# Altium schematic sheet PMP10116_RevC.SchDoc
size 431 x 279 mm; Date: Not shown in title block; ApprovedBy: Not shown in title block; CheckedBy: Not shown in title block; Author: Not shown in title block; CompanyName: Not shown in title block; Engineer: Not shown in title block; Organization: Not shown in title block; Address1: Not shown in title block; Address2: Not shown in title block; Address3: Not shown in title block; Address4: Not shown in title block; DocumentNumber: 1; Revision: Use project parameter SCH_Rev; SheetNumber: 2; SheetTotal: 3; PageSetup: Record=PageOptions¦CenterHorizontal=True¦CenterVertical=True¦PrintScale=1.00¦XCorrection=1.00¦YCorrection=1.00¦PrintKind=0¦BorderSize=5000000¦LeftOffset=0¦BottomOffset=0¦Orientation=2¦PaperLength=1000¦PaperWidth=1000¦Scale=100¦PaperSource=15¦PrintQuality=600¦MediaType=1¦DitherType=10¦PaperKind=Letter¦PrintScaleMode=1
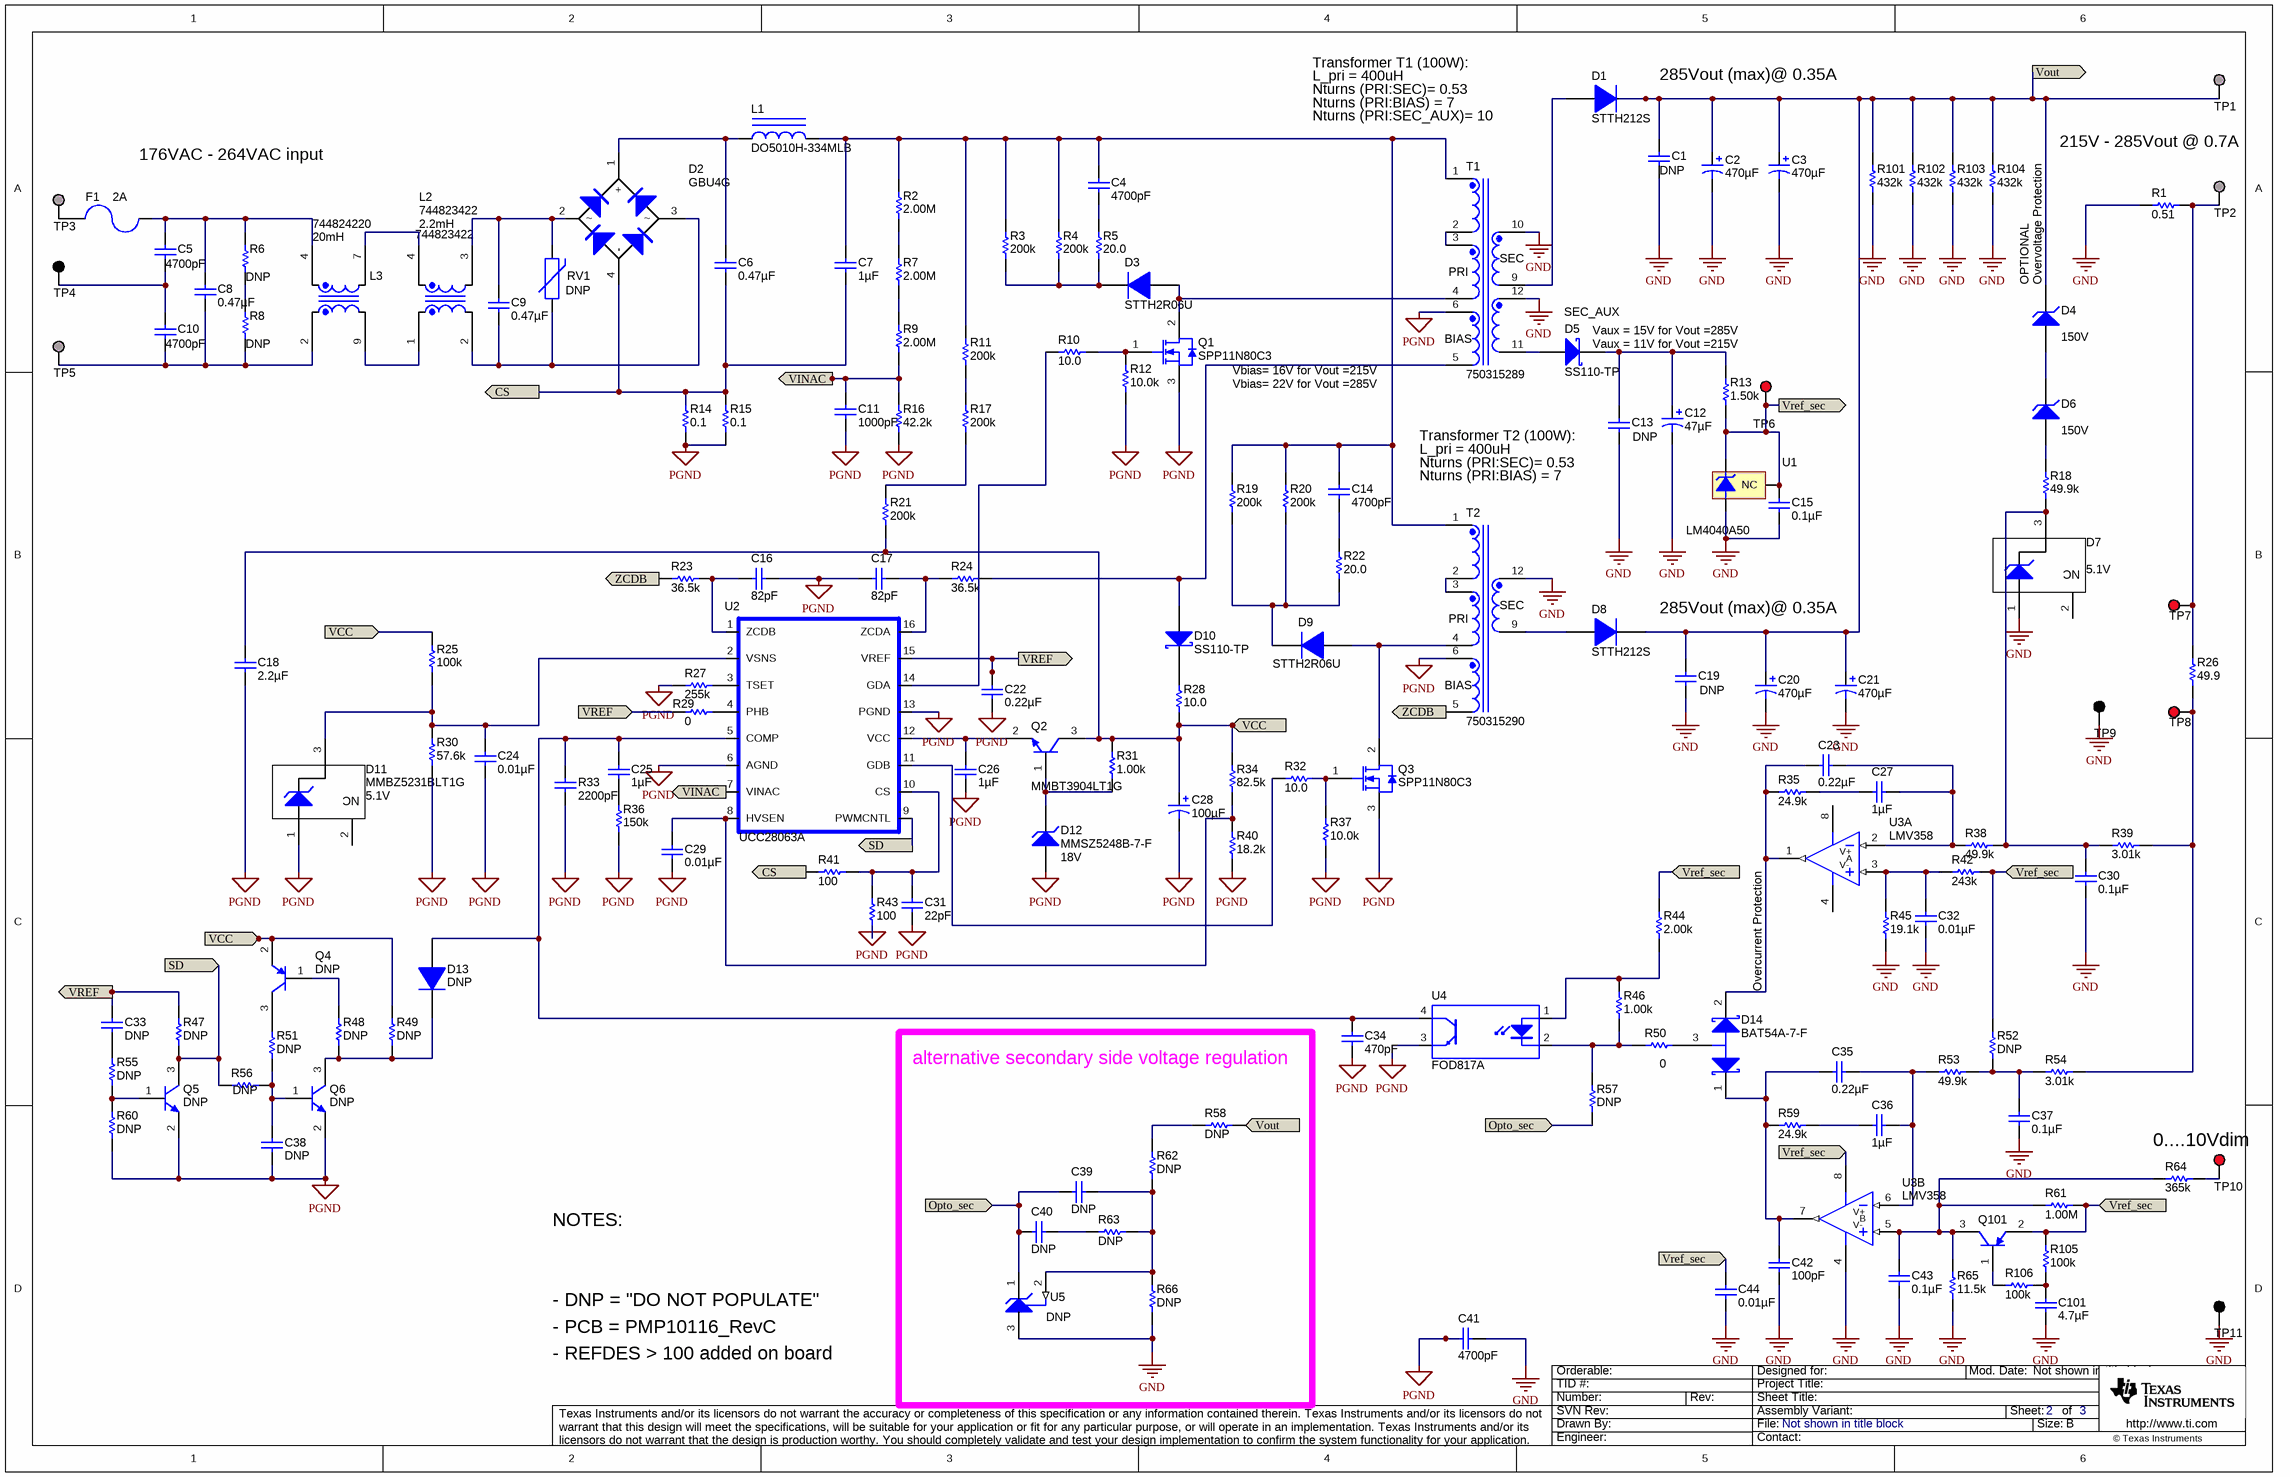
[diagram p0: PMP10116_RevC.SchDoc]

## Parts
C1  value DNP  [1210]  (hidden comment: Used in BOM report)
C2  ValueDisplayed: 470µF  [KMQ_3500x3000]  (hidden comment: EKMQ351VSN471MA30S)
C3  ValueDisplayed: 470µF  [KMQ_3500x3000]  (hidden comment: EKMQ351VSN471MA30S)
C4  ValueDisplayed: 4700pF  [1206]  (hidden comment: GRM31BR72J472KW01L)
C5  ValueDisplayed: 4700pF  [VY2_1250x500x1650]  (hidden comment: VY2472M49Y5US63V7)
C6  ValueDisplayed: 0.47µF  [B32923_16.5mm]  (hidden comment: B32923C3474M)
C7  ValueDisplayed: 1µF  [B32923_20.5mm]  (hidden comment: B32923C3105M)
C8  ValueDisplayed: 0.47µF  [B32923_16.5mm]  (hidden comment: B32923C3474K)
C9  ValueDisplayed: 0.47µF  [B32923_16.5mm]  (hidden comment: B32923C3474K)
C10  ValueDisplayed: 4700pF  [VY2_1250x500x1650]  (hidden comment: VY2472M49Y5US63V7)
C11  ValueDisplayed: 1000pF  [0603]  (hidden comment: 06035A102KAT2A)
C12  ValueDisplayed: 47µF  [SM_RADIAL_E]  (hidden comment: EEE-FC1E470P)
C13  value DNP  [1206]  (hidden comment: Used in BOM report)
C14  ValueDisplayed: 4700pF  [1206]  (hidden comment: GRM31BR72J472KW01L)
C15  ValueDisplayed: 0.1µF  [0603]  (hidden comment: 06035C104KAT2A)
C16  ValueDisplayed: 82pF  [0603]  (hidden comment: GRM1885C1H820JA01D)
C17  ValueDisplayed: 82pF  [0603]  (hidden comment: GRM1885C1H820JA01D)
C18  ValueDisplayed: 2.2µF  [1210_280]  (hidden comment: C3225X7R1H225K250AB)
C19  value DNP  [1210]  (hidden comment: Used in BOM report)
C20  ValueDisplayed: 470µF  [KMQ_3500x3000]  (hidden comment: EKMQ351VSN471MA30S)
C21  ValueDisplayed: 470µF  [KMQ_3500x3000]  (hidden comment: EKMQ351VSN471MA30S)
C22  ValueDisplayed: 0.22µF  [0805]  (hidden comment: C1608X7R1H224K080AB)
C23  ValueDisplayed: 0.22µF  [0603]  (hidden comment: GRM188R71E224KA88D)
C24  ValueDisplayed: 0.01µF  [0603]  (hidden comment: C0603C103J5RACTU)
C25  ValueDisplayed: 1µF  [0805_HV]  (hidden comment: GRM21BR71H105KA12L)
C26  ValueDisplayed: 1µF  [0805_HV]  (hidden comment: C2012X7R1H105K125AB)
C27  ValueDisplayed: 1µF  [0805_HV]  (hidden comment: GRM21BR71C105KA01L)
C28  ValueDisplayed: 100µF  [SM_RADIAL_G]  (hidden comment: EEE-FC1V101P)
C29  ValueDisplayed: 0.01µF  [0603]  (hidden comment: C0603C103J5RACTU)
C30  ValueDisplayed: 0.1µF  [0603]  (hidden comment: C0603C104K5RACTU)
C31  ValueDisplayed: 22pF  [0603]  (hidden comment: 06035A220JAT2A)
C32  ValueDisplayed: 0.01µF  [0603]  (hidden comment: GRM188R71H103KA01D)
C33  ValueDisplayed: DNP  [0805_HV]  (hidden comment: GRM21BR71H474KA88L)
C34  ValueDisplayed: 470pF  [0603]  (hidden comment: GRM188R71H471KA01D)
C35  ValueDisplayed: 0.22µF  [0603]  (hidden comment: GRM188R71E224KA88D)
C36  ValueDisplayed: 1µF  [0805_HV]  (hidden comment: GRM21BR71C105KA01L)
C37  ValueDisplayed: 0.1µF  [0603]  (hidden comment: C0603C104K5RACTU)
C38  ValueDisplayed: DNP  [0805_HV]  (hidden comment: GRM216R71H103KA01D)
C39  ValueDisplayed: DNP  [0805_HV]  (hidden comment: 08055C473JAT2A)
C40  ValueDisplayed: DNP  [0805_HV]  (hidden comment: C2012X5R1E475K125AB)
C41  ValueDisplayed: 4700pF  [VY2_1250x500x1650]  (hidden comment: VY2472M49Y5US63V7)
C42  ValueDisplayed: 100pF  [0603]  (hidden comment: C1608C0G1H101J)
C43  ValueDisplayed: 0.1µF  [0603]  (hidden comment: 06035C104KAT2A)
C44  ValueDisplayed: 0.01µF  [0603]  (hidden comment: GRM188R71H103KA01D)
C101  ValueDisplayed: 4.7µF  [1206]  (hidden comment: C3216X7R1E475K)
D1  STTH212S  [SMC]
D2  GBU4G  [GBU]
D3  STTH2R06U  [SMB]
D4  value 150V  [SMA]  (hidden comment: 3smaj5953b)
D5  SS110-TP  [SMA]
D6  value 150V  [SMA]  (hidden comment: 3smaj5953b)
D7  value 5.1V  [SOT-23]  (hidden comment: MMBZ5230BLT1G)
D8  STTH212S  [SMC]
D9  STTH2R06U  [SMB]
D10  SS110-TP  [SMA]
D11  MMBZ5231BLT1G  value 5.1V  [SOT-23]
D12  MMSZ5248B-7-F  value 18V  [SOD-123]
D13  DNP  [SOD-123]
D14  BAT54A-7-F  [SOT-23]
F1  value 2A  [FUSE_372]  (hidden comment: 38312000000)
L1  DO5010H-334MLB  [DO5010H]
L2  744823422  ValueDisplayed: 2.2mH  [IND_WE-CMB_M]
L3  744824220  value 20mH  [IND_WE-CMB_L]
Q1  SPP11N80C3  [TO-220FP]
Q2  MMBT3904LT1G  [SOT-23]
Q3  SPP11N80C3  [TO-220FP]
Q4  DNP  [SOT-23]
Q5  DNP  [SOT-23]
Q6  DNP  [SOT-23]
Q101  MMBT3906-7-F  [SOT-23]  (value not drawn)
R1  value 0.51  [1210M]  (hidden comment: MCR25JZHFLR510)
R2  ValueDisplayed: 2.00M  [0805_HV]  (hidden comment: CRCW08052M00FKEA)
R3  ValueDisplayed: 200k  [2010]  (hidden comment: CRCW2010200KJNEF)
R4  ValueDisplayed: 200k  [2010]  (hidden comment: CRCW2010200KJNEF)
R5  ValueDisplayed: 20.0  [2010]  (hidden comment: CRCW201020R0FKEF)
R6  value DNP  [1206]  (hidden comment: CRCW1206470KJNEA)
R7  ValueDisplayed: 2.00M  [0805_HV]  (hidden comment: CRCW08052M00FKEA)
R8  value DNP  [1206]  (hidden comment: CRCW1206470KJNEA)
R9  ValueDisplayed: 2.00M  [0805_HV]  (hidden comment: CRCW08052M00FKEA)
R10  ValueDisplayed: 10.0  [0805_HV]  (hidden comment: CRCW080510R0FKEA)
R11  value 200k  [1206]  (hidden comment: CRCW1206200KFKEA)
R12  ValueDisplayed: 10.0k  [0805_HV]  (hidden comment: CRCW080510K0FKEA)
R13  value 1.50k  [0603]  (hidden comment: CRCW06031K50FKEA)
R14  ValueDisplayed: 0.1  [1210M]  (hidden comment: ERJ-L14KF10CU)
R15  ValueDisplayed: 0.1  [1210M]  (hidden comment: ERJ-L14KF10CU)
R16  ValueDisplayed: 42.2k  [0805_HV]  (hidden comment: CRCW080542K2FKEA)
R17  value 200k  [1206]  (hidden comment: CRCW1206200KFKEA)
R18  ValueDisplayed: 49.9k  [0603]  (hidden comment: CRCW060349K9FKEA)
R19  ValueDisplayed: 200k  [2010]  (hidden comment: CRCW2010200KJNEF)
R20  ValueDisplayed: 200k  [2010]  (hidden comment: CRCW2010200KJNEF)
R21  value 200k  [1206]  (hidden comment: CRCW1206200KFKEA)
R22  ValueDisplayed: 20.0  [2010]  (hidden comment: CRCW201020R0FKEF)
R23  ValueDisplayed: 36.5k  [0603]  (hidden comment: CRCW060336K5FKEA)
R24  ValueDisplayed: 36.5k  [0603]  (hidden comment: CRCW060336K5FKEA)
R25  ValueDisplayed: 100k  [0603]  (hidden comment: CRCW0603100KFKEA)
R26  value 49.9  [0603]  (hidden comment: CRCW060349R9FKEA)
R27  ValueDisplayed: 255k  [0603]  (hidden comment: CRCW0603255KFKEA)
R28  value 10.0  [0805_HV]  (hidden comment: CRCW080510R0FKEA)
R29  ValueDisplayed: 0  [0603]  (hidden comment: CRCW06030000Z0EA)
R30  ValueDisplayed: 57.6k  [0603]  (hidden comment: CRCW060357K6FKEA)
R31  value 1.00k  [0603]  (hidden comment: CRCW06031K00FKEA)
R32  ValueDisplayed: 10.0  [0805_HV]  (hidden comment: CRCW080510R0FKEA)
R33  ValueDisplayed: 2200pF  [0603]  (hidden comment: C0603C222K5RACTU)
R34  ValueDisplayed: 82.5k  [0603]  (hidden comment: CRCW060382K5FKEA)
R35  ValueDisplayed: 24.9k  [0603]  (hidden comment: CRCW060324K9FKEA)
R36  ValueDisplayed: 150k  [0603]  (hidden comment: CRCW0603150KFKEA)
R37  ValueDisplayed: 10.0k  [0805_HV]  (hidden comment: CRCW080510K0FKEA)
R38  ValueDisplayed: 49.9k  [0603]  (hidden comment: RC0603FR-0749K9L)
R39  ValueDisplayed: 3.01k  [0603]  (hidden comment: CRCW06033K01FKEA)
R40  ValueDisplayed: 18.2k  [0603]  (hidden comment: CRCW060318K2FKEA)
R41  ValueDisplayed: 100  [0603]  (hidden comment: CRCW0603100RFKEA)
R42  ValueDisplayed: 243k  [0603]  (hidden comment: CRCW0603243KFKEA)
R43  ValueDisplayed: 100  [0603]  (hidden comment: CRCW0603100RFKEA)
R44  ValueDisplayed: 2.00k  [0603]  (hidden comment: CRCW06032K00FKEA)
R45  ValueDisplayed: 19.1k  [0603]  (hidden comment: CRCW060319K1FKEA)
R46  value 1.00k  [0603]  (hidden comment: CRCW06031K00FKEA)
R47  ValueDisplayed: DNP  [0603]  (hidden comment: CRCW060310K0FKEA)
R48  ValueDisplayed: DNP  [0603]  (hidden comment: CRCW060310K0FKEA)
R49  ValueDisplayed: DNP  [0603]  (hidden comment: CRCW0603200RFKEA)
R50  value 0  [0603]  (hidden comment: RC0603FR-072KL)
R51  ValueDisplayed: DNP  [0603]  (hidden comment: CRCW060310K0FKEA)
R52  DNP  [0603_HV]
R53  ValueDisplayed: 49.9k  [0603]  (hidden comment: RC0603FR-0749K9L)
R54  ValueDisplayed: 3.01k  [0603]  (hidden comment: CRCW06033K01FKEA)
R55  ValueDisplayed: DNP  [0603]  (hidden comment: CRCW0603100KFKEA)
R56  ValueDisplayed: DNP  [0603]  (hidden comment: CRCW06031K00FKEA)
R57  value DNP  [0603]  (hidden comment: CRCW06030000Z0EA)
R58  value DNP  [0603]  (hidden comment: CRCW060349R9FKEA)
R59  ValueDisplayed: 24.9k  [0603]  (hidden comment: CRCW060324K9FKEA)
R60  ValueDisplayed: DNP  [0603]  (hidden comment: CRCW0603100KFKEA)
R61  ValueDisplayed: 1.00M  [0603]  (hidden comment: CRCW06031M00FKEA)
R62  ValueDisplayed: DNP  [0603]  (hidden comment: CRCW0603200KFKEA)
R63  ValueDisplayed: DNP  [0603]  (hidden comment: CRCW060315K0FKEA)
R64  ValueDisplayed: 365k  [0603]  (hidden comment: CRCW0603365KFKEA)
R65  ValueDisplayed: 11.5k  [0603]  (hidden comment: CRCW060311K5FKEA)
R66  ValueDisplayed: DNP  [0603]  (hidden comment: CRCW06032K43FKEA)
R101  ValueDisplayed: 432k  [CMF50]  (hidden comment: CMF50432K00FHEB)
R102  ValueDisplayed: 432k  [CMF50]  (hidden comment: CMF50432K00FHEB)
R103  ValueDisplayed: 432k  [CMF50]  (hidden comment: CMF50432K00FHEB)
R104  ValueDisplayed: 432k  [CMF50]  (hidden comment: CMF50432K00FHEB)
R105  ValueDisplayed: 100k  [0603]  (hidden comment: CRCW0603100KFKEA)
R106  ValueDisplayed: 100k  [0603]  (hidden comment: CRCW0603100KFKEA)
RV1  value DNP  [VAR_S10K275E2]  (hidden comment: S20K275)
T1  750315289  [WURTH_750315289_90]
T2  750315290  [WURTH_750315289_90]
TP1  Suggest using a net name here  [Keystone1503-2]  (value not drawn)
TP2  Suggest using a net name here  [Keystone1503-2]  (value not drawn)
TP3  Suggest using a net name here  [Keystone1503-2]  (value not drawn)
TP4  5011  [Keystone5011]  (value not drawn)
TP5  Suggest using a net name here  [Keystone1503-2]  (value not drawn)
TP6  5000  [Keystone5000]  (value not drawn)
TP7  5000  [Keystone5000]  (value not drawn)
TP8  5000  [Keystone5000]  (value not drawn)
TP9  5001  [Keystone5001]  (value not drawn)
TP10  5000  [Keystone5000]  (value not drawn)
TP11  5001  [Keystone5001]  (value not drawn)
U1  LM4040A50  [MF03A_N]
U2  UCC28063A  [D0016A_N]
U3  LMV358  [M08A_L]  (parts A,B of 2)
U4  FOD817A  [DIP-4]
U5  value DNP  [DBZ0003A_N]  (hidden comment: TL431AIDBZT)

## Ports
CS (in), CS (out), Opto_sec (in), SD (in), SD (out), VCC (in), VCC (out), VINAC (in), VINAC (out), Vout (in), Vout (out), VREF (in), VREF (out), Vref_sec (in), Vref_sec (out), ZCDB (in), ZCDB (out)

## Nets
GND: C1.2 C2.2(-) C3.2(-) C12.2(-) C13.2 C15.2 C19.2 C20.2(-) C21.2(-) C30.2 C32.2 C37.2 C41.2 C42.2 C43.2 C44.1 C101.2 D7.1(A) R1.2 R45.1 R65.1 R66.1 R101.1 R102.1 R103.1 R104.1 T1.10 T1.12 T2.12 TP9.1 TP11.1 U1.2(-V) U3.4(V-) U5.3(ANODE)
PGND: C11.2 C16.2 C17.1 C18.2 C22.2 C24.2 C26.2 C28.2(-) C29.2 C31.2 C34.2 C38.2 C41.1 D11.1(A) D12.2(A) Q1.3(S) Q3.3(S) Q5.2(E) Q6.2(E) R12.1 R14.1 R15.1 R16.1 R27.1 R30.1 R33.2 R36.1 R37.1 R40.1 R43.1 R60.1 T1.6 T2.6 U2.6(AGND) U2.13(PGND) U4.3(E)
CS: C6.2 C7.2 D2.4(-) R14.2 R15.2 R41.2 ; port CS
Opto_sec: C39.1 C40.2 R57.2 U5.1(CATHODE) ; port Opto_sec
SD: Q5.3(C) R47.1 R56.2 U2.9(PWMCNTL) ; port SD
VCC: C18.1 C28.1(+) Q2.3(C) Q4.2(E) R21.1 R25.2 R28.1 R31.2 R34.2 R49.2 ; port VCC
VINAC: C11.1 R9.1 R16.2 U2.7(VINAC) ; port VINAC
Vout: C1.1 C2.1(+) C3.1(+) C19.1 C20.1(+) C21.1(+) D1.1(K) D4.1(K) D8.1(K) R58.1 R101.2 R102.2 R103.2 R104.2 TP1.1 ; port Vout
VREF: C22.1 C33.1 R29.1 R47.2 U2.15(VREF) ; port VREF
Vref_sec: C15.1 C44.2 Q101.2(E) R13.1 R42.2 R44.1 R52.2 R61.2 R105.2 TP6.1 U1.1(+V) U1.3(NC) U3.8(V+) ; port Vref_sec
ZCDB: R23.1 T2.5 ; port ZCDB
NetC4_1: C4.1 C7.1 C14.1 L1.2 R2.2 R3.2 R4.2 R11.2 R19.2 R20.2 T1.1 T2.1
NetC4_2: C4.2 R5.2
NetC5_1: C5.1 C8.1 F1.1 L3.4 R6.2
NetC5_2: C5.2 C10.1 TP4.1
NetC6_1: C6.1 D2.1(+) L1.1
NetC8_2: C8.2 C10.2 L3.2 R8.1 TP5.1
NetC9_1: C9.1 D2.2 L2.3 RV1.2
NetC9_2: C9.2 D2.3 L2.2 RV1.1
NetC12_1: C12.1(+) C13.1 D5.1(K) R13.2
NetC14_2: C14.2 R22.2
NetC16_1: C16.1 R23.2 U2.1(ZCDB)
NetC17_2: C17.2 R24.2 U2.16(ZCDA)
NetC23_1: C23.1 D14.2(K2) R35.2 U3.1(OUT)
NetC23_2: C23.2 C27.1 R38.2 U3.2(IN-)
NetC24_1: C24.1 D11.3(K) R25.1 R30.2 U2.2(VSNS)
NetC25_1: C25.1 C34.1 D13.2(A) R33.1 U2.5(COMP) U4.4(C)
NetC25_2: C25.2 R36.2
NetC26_1: C26.1 Q2.2(E) U2.12(VCC)
NetC27_2: C27.2 R35.1
NetC29_1: C29.1 R34.1 R40.2 U2.8(HVSEN)
NetC30_1: C30.1 D7.3(K) R18.1 R38.1 R39.1
NetC31_1: C31.1 R41.1 R43.2 U2.10(CS)
NetC32_1: C32.1 R42.1 R45.2 U3.3(IN+)
NetC33_2: C33.2 R55.2
NetC35_1: C35.1 C42.1 D14.1(K1) R59.2 U3.7(OUT)
NetC35_2: C35.2 C36.1 R53.2 U3.6(IN-)
NetC36_2: C36.2 R59.1
NetC37_1: C37.1 R52.1 R53.1 R54.1
NetC38_1: C38.1 Q6.1(B) R51.1 R56.1
NetC39_2: C39.2 R62.1 R63.1 R66.2 U5.2(REF)
NetC40_1: C40.1 R63.2
NetC43_1: C43.1 Q101.3(C) R61.1 R64.1 R65.2 U3.5(IN+)
NetC101_1: C101.1 R105.1 R106.1
NetD1_2: D1.2(A) T1.9
NetD3_1: D3.1(K) R3.1 R4.1 R5.1
NetD3_2: D3.2(A) Q1.2(D) T1.4
NetD4_2: D4.2(A) D6.1(K)
NetD5_2: D5.2(A) T1.11
NetD6_2: D6.2(A) R18.2
NetD8_2: D8.2(A) T2.9
NetD9_1: D9.1(K) R19.1 R20.1 R22.1
NetD9_2: D9.2(A) Q3.2(D) T2.4
NetD10_1: D10.1(K) R28.2
NetD10_2: D10.2(A) R24.1 T1.5
NetD12_1: D12.1(K) Q2.1(B) R31.1
NetD13_1: D13.1(K) Q6.3(C) R48.1 R49.1
NetD14_3: D14.3(A) R50.1
NetF1_2: F1.2 TP3.1
NetL2_1: L2.1 L3.9
NetL2_4: L2.4 L3.7
NetQ1_1: Q1.1(G) R10.2 R12.2
NetQ3_1: Q3.1(G) R32.2 R37.2
NetQ4_1: Q4.1(B) R48.2
NetQ4_3: Q4.3(C) R51.2
NetQ5_1: Q5.1(B) R55.1 R60.2
NetQ101_1: Q101.1(B) R106.2
NetR1_1: R1.1 R26.2 TP2.1 TP7.1
NetR2_1: R2.1 R7.2
NetR6_1: R6.1 R8.2
NetR7_1: R7.1 R9.2
NetR10_1: R10.1 U2.14(GDA)
NetR11_1: R11.1 R17.2
NetR17_1: R17.1 R21.2
NetR26_1: R26.1 R39.2 R54.2 TP8.1
NetR27_2: R27.2 U2.3(TSET)
NetR29_2: R29.2 U2.4(PHB)
NetR32_1: R32.1 U2.11(GDB)
NetR44_2: R44.2 R46.2 U4.1(A)
NetR46_1: R46.1 R50.2 R57.1 U4.2(K)
NetR58_2: R58.2 R62.2
NetR64_2: R64.2 TP10.1
NetT1_2: T1.2 T1.3
NetT2_2: T2.2 T2.3

Not connected (* = marked no-connect by the designer): D7 2(NC); D11 2(NC)

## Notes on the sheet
- Transformer T1 (100W):
- L_pri = 400uH
- Nturns (PRI:SEC)= 0.53
- 285Vout (max)@ 0.35A
- 176VAC - 264VAC input
- Nturns (PRI:SEC_AUX)= 10
- Nturns (PRI:BIAS) = 7
- 215V - 285Vout @ 0.7A
- (near T1) PRI
- (near T1) SEC
- (near D4) OPTIONAL
- Overvoltage Protection
- (near T1) BIAS
- (near D5) SEC_AUX
- (near D5) Vaux = 15V for Vout =285V
- (near D5) Vaux = 11V for Vout =215V
- Vbias= 16V for Vout =215V
- Vbias= 22V for Vout =285V
- Transformer T2 (100W):
- (near T2) PRI
- (near T2) SEC
- (near T2) BIAS
- Overcurrent Protection
- alternative secondary side voltage regulation
- (near TP10) 0....10Vdim
- NOTES:
- - DNP = "DO NOT POPULATE"
- - PCB = PMP10116_RevC
- - REFDES > 100 added on board

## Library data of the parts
C1 C13 C19 = Capacitor: CAP, CERM, xxxF, xxV, [TempCo], xx%, [PackageReference]; Polarized: N; U/M: EA
C2 C3 C20 C21 = EKMQ351VSN471MA30S: CAP, AL, 470 µF, 350 V, +/- 20%,  ohm, TH; Manufacturer: Chemi-Con; Polarized: Y; CompType: Capacitor; Value: 470uF; U/M: EA; Cap_F: 0.00047; Tolerance_%: 20; Value1: Unknown; VDC_V: 350; Value2: 350V; IRMS_A: 1.4; TaMin_C: -25; TaMax_C: 105; Cap_Case: 35x30mm
C4 C14 = GRM31BR72J472KW01L: CAP, CERM, 4700 pF, 630 V, +/- 10%, X7R, 1206; Manufacturer: MuRata; Polarized: N; CompType: Capacitor; Value: 4700pF; U/M: EA; Cap_F: 0.0000000047; Tolerance_%: 10; Value1: Unknown; VDC_V: 630; Value2: 630V; TaMin_C: -55; TaMax_C: 125
C5 C10 C41 = VY2472M49Y5US63V7: CAP, CERM, 4700 pF, 440 V, +/- 20%, Y5U, TH, 12.5x5mm; Manufacturer: Vishay-Bccomponents; Polarized: N; CompType: Capacitor; Value: 4700pF; U/M: EA; Cap_F: 0.0000000047; Tolerance_%: 20; Value1: Unknown; VDC_V: 440; Value2: 440V; TaMin_C: -40; TaMax_C: 125; Cap_Case: 12.5x5x16.5
C6 = B32923C3474M: CAP, Film, 0.47 µF, 630 V, +/- 20%, TH; Manufacturer: EPCOS Inc; Polarized: N; CompType: Capacitor; Value: 0.47uF; U/M: EA; Cap_F: 0.00000047; Tolerance_%: 20; Value1: Unknown; VDC_V: 630; Value2: 630V; TaMax_C: 110
C7 = B32923C3105M: CAP, Film, 1 µF, 630 V, +/- 20%, 0.018 ohm, TH; Manufacturer: EPCOS Inc; Polarized: N; CompType: Capacitor; Value: 1uF; U/M: EA; Cap_F: 0.000001; Tolerance_%: 20; VDC_V: 630; Value2: 630V; ESR_ohm: 0.018; IRMS_A: 0.097; TaMax_C: 110
C8 C9 = B32923C3474K: CAP, Film, 0.47 µF, 630 V, +/- 10%, TH; Manufacturer: TDK; Polarized: N; CompType: Capacitor; Value: 0.47uF; U/M: EA; Cap_F: 0.00000047; Tolerance_%: 10; Value1: Unknown; VDC_V: 630; Value2: 630V; TaMax_C: 110
C11 = 06035A102KAT2A: CAP, CERM, 1000 pF, 50 V, +/- 10%, C0G/NP0, 0603; Manufacturer: AVX; Polarized: N; CompType: Capacitor; Value: 1000pF; U/M: EA; Cap_F: 0.000000001; Tolerance_%: 10; ESR_ohm: 0.048; Value1: 0.048 ohm; VDC_V: 50; Value2: 50V; TaMin_C: -55; TaMax_C: 125
C12 = EEE-FC1E470P: CAP, AL, 47uF, 25V, +/-20%, 0.4 ohm, SMD; Manufacturer: Panasonic; Polarized: Y; CompType: Capacitor; U/M: EA; Cap_F: 0.000047; Tolerance_%: 20; Value1: 0.4 ohm; VDC_V: 25; ESR_Ohm: 0.4; IRMS_A: 0.15; TaMin_C: -40; TaMax_C: 105; Cap_Case: E
C15 C43 = 06035C104KAT2A: CAP, CERM, 0.1uF, 50V, +/-10%, X7R, 0603; Manufacturer: AVX; Polarized: N; CompType: Capacitor; U/M: EA; Cap_F: 0.0000001; Tolerance_%: 10; Value1: Unknown; VDC_V: 50; TaMin_C: -55; TaMax_C: 125
C16 C17 = GRM1885C1H820JA01D: CAP, CERM, 82 pF, 50 V, +/- 5%, C0G/NP0, 0603; Manufacturer: MuRata; Polarized: N; CompType: Capacitor; Value: 82pF; U/M: EA; Cap_F: 0.000000000082; Tolerance_%: 5; Value1: Unknown; VDC_V: 50; Value2: 50V; TaMin_C: -55; TaMax_C: 125
C18 = C3225X7R1H225K250AB: CAP, CERM, 2.2 µF, 50 V, +/- 10%, X7R, 1210; Manufacturer: TDK; Polarized: N; CompType: Capacitor; Value: 2.2uF; U/M: EA; Cap_F: 0.0000022; Tolerance_%: 10; Value1: Unknown; VDC_V: 50; Value2: 50V; TaMin_C: -55; TaMax_C: 125; Cap_Case: 1210
C22 = GRM21BR71H224KA01L: CAP, CERM, 0.22 µF, 50 V, +/- 10%, X7R, 0805; Manufacturer: MuRata; Polarized: N; CompType: Capacitor; Value: 0.22uF; U/M: EA; Cap_F: 0.00000022; Tolerance_%: 10; Value1: Unknown; VDC_V: 50; Value2: 50V; TaMin_C: -55; TaMax_C: 125
C23 C35 = GRM188R71E224KA88D: CAP, CERM, 0.22 µF, 25 V, +/- 10%, X7R, 0603; Manufacturer: MuRata; Polarized: N; CompType: Capacitor; Value: 0.22uF; U/M: EA; Cap_F: 0.00000022; Tolerance_%: 10; Value1: Unknown; VDC_V: 25; Value2: 25V; TaMin_C: -55; TaMax_C: 125
C24 C29 = C0603C103J5RACTU: CAP, CERM, 0.01 µF, 50 V, +/- 5%, X7R, 0603; Manufacturer: Kemet; Polarized: N; CompType: Capacitor; Value: 0.01uF; U/M: EA; Cap_F: 0.00000001; Tolerance_%: 5; Value1: Unknown; VDC_V: 50; Value2: 50V; TaMin_C: -55; TaMax_C: 125
C25 = GRM21BR71H105KA12L: CAP, CERM, 1 µF, 50 V, +/- 10%, X7R, 0805; Manufacturer: MuRata; Polarized: N; CompType: Capacitor; Value: 1uF; U/M: EA; Cap_F: 0.000001; Tolerance_%: 10; Value1: Unknown; VDC_V: 50; Value2: 50V; TaMin_C: -55; TaMax_C: 125; Cap_Case: 0805
C26 = C2012X7R1H105K125AB: CAP, CERM, 1 µF, 50 V, +/- 10%, X7R, 0805; Manufacturer: TDK; Polarized: N; CompType: Capacitor; Value: 1uF; U/M: EA; Cap_F: 0.000001; Tolerance_%: 10; Value1: Unknown; VDC_V: 50; Value2: 50V; TaMin_C: -55; TaMax_C: 125; Cap_Case: 0805
C27 C36 = GRM21BR71C105KA01L: CAP, CERM, 1 µF, 16 V, +/- 10%, X7R, 0805; Manufacturer: MuRata; Polarized: N; CompType: Capacitor; Value: 1uF; U/M: EA; Cap_F: 0.000001; Tolerance_%: 10; ESR_ohm: 0.003; Value1: 0.003 ohm; VDC_V: 16; Value2: 16V; TaMin_C: -55; TaMax_C: 125; Cap_Case: 0805
C28 = EEE-FC1V101P: CAP, AL, 100 µF, 35 V, +/- 20%, 0.15 ohm, SMD; Manufacturer: Panasonic; Polarized: Y; CompType: Capacitor; Value: 100uF; U/M: EA; Cap_F: 0.0001; Tolerance_%: 20; VDC_V: 35; Value2: 35V; ESR_ohm: 0.15; IRMS_A: 0.22; TaMin_C: -40; TaMax_C: 105; Cap_Case: G
C30 C37 = C0603C104K5RACTU: CAP, CERM, 0.1 µF, 50 V, +/- 10%, X7R, 0603; Manufacturer: Kemet; Polarized: N; CompType: Capacitor; Value: 0.1uF; U/M: EA; Cap_F: 0.0000001; Tolerance_%: 10; Value1: Unknown; VDC_V: 50; Value2: 50V; TaMin_C: -55; TaMax_C: 125
C31 = 06035A220JAT2A: CAP, CERM, 22 pF, 50 V, +/- 5%, C0G/NP0, 0603; Manufacturer: AVX; Polarized: N; CompType: Capacitor; Value: 22pF; U/M: EA; Cap_F: 0.000000000022; Tolerance_%: 5; ESR_ohm: 0.259; Value1: 0.259 ohm; VDC_V: 50; Value2: 50V; TaMin_C: -55; TaMax_C: 125
C32 C44 = GRM188R71H103KA01D: CAP, CERM, 0.01uF, 50V, +/-10%, X7R, 0603; Manufacturer: MuRata; Polarized: N; CompType: Capacitor; U/M: EA; Cap_F: 0.00000001; Tolerance_%: 10; Value1: Unknown; VDC_V: 50; TaMin_C: -55; TaMax_C: 125
C33 = GRM21BR71H474KA88L: CAP, CERM, 0.47 µF, 50 V, +/- 10%, X7R, 0805; Manufacturer: MuRata; Polarized: N; CompType: Capacitor; Value: 0.47uF; U/M: EA; Cap_F: 0.00000047; Tolerance_%: 10; Value1: Unknown; VDC_V: 50; Value2: 50V; TaMin_C: -55; TaMax_C: 125; Cap_Case: 0805
C34 = GRM188R71H471KA01D: CAP, CERM, 470 pF, 50 V, +/- 10%, X7R, 0603; Manufacturer: MuRata; Polarized: N; CompType: Capacitor; Value: 470pF; U/M: EA; Cap_F: 0.00000000047; Tolerance_%: 10; Value1: Unknown; VDC_V: 50; Value2: 50V; TaMin_C: -55; TaMax_C: 125
C38 = GRM216R71H103KA01D: CAP, CERM, 0.01 µF, 50 V, +/- 10%, X7R, 0805; Manufacturer: MuRata; Polarized: N; CompType: Capacitor; Value: 0.01uF; U/M: EA; Cap_F: 0.00000001; Tolerance_%: 10; Value1: Unknown; VDC_V: 50; Value2: 50V; TaMin_C: -55; TaMax_C: 125; Cap_Case: 0805
C39 = 08055C473JAT2A: CAP, CERM, 0.047 µF, 50 V, +/- 5%, X7R, 0805; Manufacturer: AVX; Polarized: N; CompType: Capacitor; Value: 0.047uF; U/M: EA; Cap_F: 0.000000047; Tolerance_%: 5; ESR_ohm: 0.035; Value1: 0.035 ohm; VDC_V: 50; Value2: 50V; TaMin_C: -55; TaMax_C: 125; Cap_Case: 0805
C40 = C2012X5R1E475K125AB: CAP, CERM, 4.7 µF, 25 V, +/- 10%, X5R, 0805; Manufacturer: TDK; Polarized: N; CompType: Capacitor; Value: 4.7uF; U/M: EA; Cap_F: 0.0000047; Tolerance_%: 10; Value1: Unknown; VDC_V: 25; Value2: 25V; TaMin_C: -55; TaMax_C: 85; Cap_Case: 0805
C42 = C1608C0G1H101J: CAP, CERM, 100 pF, 50 V, +/- 5%, C0G/NP0, 0603; Manufacturer: TDK; Polarized: N; CompType: Capacitor; Value: 100pF; U/M: EA; Cap_F: 0.0000000001; Tolerance_%: 5; ESR_ohm: 0.1679; Value1: 0.1679 ohm; VDC_V: 50; Value2: 50V; TaMin_C: -55; TaMax_C: 125
C101 = C3216X7R1E475K: CAP, CERM, 4.7 µF, 25 V, +/- 10%, X7R, 1206; Manufacturer: TDK; Polarized: N; CompType: Capacitor; Value: 4.7uF; U/M: EA; Cap_F: 0.0000047; Tolerance_%: 10; ESR_ohm: 0.0063; Value1: 0.0063 ohm; VDC_V: 25; Value2: 25V; TaMin_C: -55; TaMax_C: 125
D1 D8 = MURS360T3G: Diode, Ultrafast, 1200V, SMC; Manufacturer: ST; U/M: EA; RJC_CperW: 11; Reverse Recovery Time (trr): 75ns; Current - Reverse Leakage @ Vr: 10µA @ 1200V
D2 = GBU4K-E3/45: Diode, Switching-Bridge, 400 V, 4 A, TH; Manufacturer: Vishay-Semiconductor; U/M: EA; Vf_V: 1; Value: 400V; Value1: 4A; Value2: 1V; Io_A: 4; TJmax_C: 150; RJC_CperW: 4.2
D3 D9 = STTH1R06U: Diode, Superfast Rectifier, 600 V, 2A, SMB; Manufacturer: ST Microelectronics; U/M: EA; Value: 600V; Io_A: 1; Vr_V: 600; TJmax_C: 175; RJC_CperW: 25; Speed: Fast Recovery =< 500ns, > 200mA (Io); Reverse Recovery Time (trr): 50ns; Current - Reverse Leakage @ Vr: 2µA @ 600V
D4 D6 = 3SMAJ5941B-TP: Diode, Zener, 150 V, 3 W, SMA; Manufacturer: Micro Commercial Components; SymbolCreator: a0412235; U/M: EA; Power_W: 3; Vz_V: 47; Value1: 3W; Tolerance_%: ±5%; Impedance (Max) (Zzt): 600 Ohm; Current - Reverse Leakage @ Vr: 1µA @ 114V
D5 D10 = SS110-TP: Diode, Schottky, 100V, 1A, SMA; Manufacturer: Micro Commercial Components; U/M: EA; Vf_V: 0.85; Value2: 0.85V; Io_A: 1; Vr_V: 100; TJmax_C: 125
D7 = MMBZ5230BLT1G: Diode, Zener, 4.7V, 225mW, SOT-23; Manufacturer: ON Semiconductor; U/M: EA; Power_W: 0.225; Vz_V: 4.7; Value1: 0.225W; RJA_CperW: 556
D11 = MMBZ5231BLT1G: Diode, Zener, 5.1 V, 225 mW, SOT-23; Manufacturer: ON Semiconductor; U/M: EA; Power_W: 0.225; Vz_V: 5.1; Value1: 0.225W; RJA_CperW: 556
D12 = MMSZ5248B-7-F: Diode, Zener, 18 V, 500 mW, SOD-123; Manufacturer: Diodes Inc.; SymbolCreator: a0412235; U/M: EA; Power_W: 0.5; Vz_V: 18; Value1: 0.5W; RJA_CperW: 350
D13 = 1N4148W-TP: Diode, Switching, 100 V, 0.15 A, SOD-123; Manufacturer: Micro Commercial Components; U/M: EA; Vf_V: 1.25; Value: 100V; Value1: 0.15A; Value2: 1.25V; Io_A: 0.15; Vr_V: 100; TJmax_C: 150
D14 = BAT54A-7-F: Diode, Schottky, 30 V, 0.2 A, SOT-23; Manufacturer: Diodes Inc.; U/M: EA; Vf_V: 0.65; Value: 30V; Value1: 0.2A; Value2: 0.65V; Io_A: 0.2; Vr_V: 30; TJmax_C: 125
F1 = 37211000001: Fuse, 2A, 300 V, TH; Manufacturer: Littelfuse; U/M: EA; OpeningTime_200%_max: 2; Irating_A: 1; Vdrop: 0.11; Soldering_Wave_MaxTemp_C: 260; Soldering_Wave_MaxTime_s: 5; Fuse Type: Board Mount (Cartridge Style Excluded); Voltage Rating - AC: 300V; Response Time: Slow; Breaking Capacity @ Rated Voltage: 100A; Melting I²t: 12; Approvals: cULus, PSE/JET
L1 = DO5010H-334MLB: Inductor, Drum Core, Ferrite, 330 µH, 1 A, 0.56 ohm, SMD; Manufacturer: Coilcraft; Value: 330uH; Ind_H: 330.0E-6; ValueDisplayed: 330µH; Imax_A: 1; Irms: 1A @ 40C rise; Isat: 1.9A @ 10% inductance drop; DCR_ohm: 0.56; Value2: 1A
L2 = 744823210: Coupled inductor, 2.2 mH,; Manufacturer: Wurth Elektronik eiSos; SymbolCreator: a0412235; Ind_H: 10.0E-3; DCR_ohm: 0.125; Isat: 2; Tolerance_%: 30; Value: 2.2mH; Filter Type: Power Line; Irms: 1.5A
L3 = 744824310: Coupled inductor, 20 mH; Manufacturer: Wurth Elektronik; SymbolCreator: a0799628; Ind_H: 10.0E-3; DCR_ohm: 0.105; Isat: 3; Tolerance_%: 30
Q1 Q3 = SPA11N80C3: MOSFET, N-CH, 800 V, 11 A, TO-220FP; Manufacturer: Infineon Technologies; Alternate Manufacturer: None; U/M: EA; ChType: N; Value: 800V; VdsMax_V: 800; Value1: ? ohm; Value2: 64 nC; QgTyp_nC: 64; Vgs_V: 20; IdsMax_A: 11
Q2 = MMBT3904LT1G, ON Semiconductor: Transistor, NPN, 40V, 0.2A, SOT-23; CompType: BJT; PNP: 0; NPN: 1; Vceo_V: 40; Vcesat1_V: 0.3; Value: 0.3V; IcRated_A: 0.2; HfeMax: 400; TaMin_C: -55; TaMax_C: 150; U/M: EA
Q4 Q101 = MMBT3906-7-F, Diodes Inc.: Transistor, PNP, 40 V, 0.2 A, SOT-23; CompType: BJT; PNP: 1; NPN: 0; Vceo_V: 40; Vcesat1_V: 0.25; Value: 40 V; IcRated_A: 0.2; Value1: 0.2 A; HfeMax: 400; TaMin_C: -55; TaMax_C: 150; U/M: EA
Q5 Q6 = MMBT3904, Fairchild Semiconductor: Transistor, NPN, 40 V, 0.2 A, SOT-23; CompType: BJT; PNP: 0; NPN: 1; Vceo_V: 40; Vcesat1_V: 0.2; Value: 40 V; Value1: 0.2 A; HfeMax: 300; TaMin_C: -55; TaMax_C: 150; U/M: EA
R1 = MCR25JZHFLR510: RES, 0.51 ohm, 1%, 0.5W, 1210; Manufacturer: Rohm; CompType: Resistor; Value_Code: R510; Tolerance_%: 1; Power_W: 0.5; TempCo: 200 ppm/C; EIA_Code: E96; U/M: EA
R2 R7 R9 = CRCW08052M00FKEA: RES, 2.00 M, 1%, 0.125 W, 0805; Manufacturer: Vishay-Dale; CompType: Resistor; Value: 2.00Meg; Res_ohm: 2000000; Value_Code: 2M00; Tolerance_%: 1; Power_W: 0.125; Value2: 0.125W; VDC_V: 150; TempCo: 100 ppm/C; EIA_Code: E96; U/M: EA
R3 R4 R19 R20 = CRCW2010200KJNEF: RES, 200 k, 5%, 0.75 W, 2010; Manufacturer: Vishay-Dale; CompType: Resistor; Value: 200k; Res_ohm: 200000; Tolerance_%: 5; Power_W: 0.75; Value2: 0.75W; VDC_V: 400; TempCo: 200 ppm/C; EIA_Code: E24; U/M: EA
R5 R22 = CRCW201020R0FKEF: RES, 20.0, 1%, 0.75 W, 2010; Manufacturer: Vishay-Dale; CompType: Resistor; Value: 20.0; Res_ohm: 20; Value_Code: 20R0; Tolerance_%: 1; Power_W: 0.75; Value2: 0.75W; VDC_V: 400; TempCo: 100 ppm/C; EIA_Code: E96; U/M: EA
R6 R8 = CRCW1206470KJNEA: RES, 470 k, 5%, 0.25 W, 1206; Manufacturer: Vishay-Dale; CompType: Resistor; Res_ohm: 470000; Value_Code: 470k; Tolerance_%: 5; Power_W: 0.25; Value2: 0.25W; VDC_V: 200; TempCo: 200 ppm/C; EIA_Code: E24; U/M: EA
R10 R32 = CRCW080510R0FKEA: RES, 10.0, 1%, 0.125 W, 0805; Manufacturer: Vishay-Dale; CompType: Resistor; Value: 10.0; Res_ohm: 10; Value_Code: 10R0; Tolerance_%: 1; Power_W: 0.125; Value2: 0.125W; VDC_V: 150; TempCo: 100 ppm/C; EIA_Code: E96; U/M: EA
R11 R17 R21 = CRCW1206200KFKEA: RES, 200k ohm, 1%, 0.25W, 1206; Manufacturer: Vishay-Dale; CompType: Resistor; Res_ohm: 200000; Tolerance_%: 1; Power_W: 0.25; VDC_V: 200; TempCo: 100 ppm/C; EIA_Code: E96; U/M: EA
R12 R37 = CRCW080510K0FKEA: RES, 10.0 k, 1%, 0.125 W, 0805; Manufacturer: Vishay-Dale; CompType: Resistor; Value: 10.0k; Res_ohm: 10000; Value_Code: 10k0; Tolerance_%: 1; Power_W: 0.125; Value2: 0.125W; VDC_V: 150; TempCo: 100 ppm/C; EIA_Code: E96; U/M: EA
R13 = CRCW06031K50FKEA: RES, 1.50k ohm, 1%, 0.1W, 0603; Manufacturer: Vishay-Dale; CompType: Resistor; Res_ohm: 1500; Value_Code: 1k50; Tolerance_%: 1; Power_W: 0.1; VDC_V: 75; TempCo: 100 ppm/C; EIA_Code: E96; U/M: EA
R14 R15 = ERJ-L14KF10CU: RES, 0.1, 1%, 0.33 W, 1210; Manufacturer: Panasonic; CompType: Resistor; Value: 0.1; Value_Code: R100; Tolerance_%: 1; Power_W: 0.33; Value2: 0.33W; TempCo: 100 ppm/C; EIA_Code: E96; U/M: EA
R16 = CRCW080542K2FKEA: RES, 42.2 k, 1%, 0.125 W, 0805; Manufacturer: Vishay-Dale; CompType: Resistor; Value: 42.2k; Res_ohm: 42200; Value_Code: 42k2; Tolerance_%: 1; Power_W: 0.125; Value2: 0.125W; VDC_V: 150; TempCo: 100 ppm/C; EIA_Code: E96; U/M: EA
R18 = CRCW060349K9FKEA: RES, 49.9 k, 1%, 0.1 W, 0603; Manufacturer: Vishay-Dale; CompType: Resistor; Value: 49.9k; Res_ohm: 49900; Value_Code: 49k9; Tolerance_%: 1; Power_W: 0.1; Value2: 0.1W; VDC_V: 75; TempCo: 100 ppm/C; EIA_Code: E96; U/M: EA
R23 R24 = CRCW060336K5FKEA: RES, 36.5 k, 1%, 0.1 W, 0603; Manufacturer: Vishay-Dale; CompType: Resistor; Value: 36.5k; Res_ohm: 36500; Value_Code: 36k5; Tolerance_%: 1; Power_W: 0.1; Value2: 0.1W; VDC_V: 75; TempCo: 100 ppm/C; EIA_Code: E96; U/M: EA
R25 R55 R60 R105 R106 = CRCW0603100KFKEA: RES, 100 k, 1%, 0.1 W, 0603; Manufacturer: Vishay-Dale; CompType: Resistor; Value: 100k; Res_ohm: 100000; Tolerance_%: 1; Power_W: 0.1; Value2: 0.1W; VDC_V: 75; TempCo: 100 ppm/C; EIA_Code: E96; U/M: EA
R26 = CRCW060349R9FKEA: RES, 49.9 ohm, 1%, 0.1W, 0603; Manufacturer: Vishay-Dale; CompType: Resistor; Value_Code: 49R9; Tolerance_%: 1; Power_W: 0.1; VDC_V: 75; TempCo: 100 ppm/C; EIA_Code: E96; U/M: EA
R27 = CRCW0603255KFKEA: RES, 255 k, 1%, 0.1 W, 0603; Manufacturer: Vishay-Dale; CompType: Resistor; Value: 255k; Res_ohm: 255000; Tolerance_%: 1; Power_W: 0.1; Value2: 0.1W; VDC_V: 75; TempCo: 100 ppm/C; EIA_Code: E96; U/M: EA
R28 = CRCW080510R0FKEA: RES, 10.0 ohm, 1%, 0.125W, 0805; Manufacturer: Vishay-Dale; CompType: Resistor; Res_ohm: 10; Value_Code: 10R0; Tolerance_%: 1; Power_W: 0.125; VDC_V: 150; TempCo: 100 ppm/C; EIA_Code: E96; U/M: EA
R29 = CRCW06030000Z0EA: RES, 0, 5%, 0.1 W, 0603; Manufacturer: Vishay-Dale; CompType: Resistor; Value: 0; Value_Code: 0000; Tolerance_%: 5; Power_W: 0.1; Value2: 0.1W; VDC_V: 75; TempCo: 200 ppm/C; EIA_Code: E24; U/M: EA
R30 = CRCW060357K6FKEA: RES, 57.6 k, 1%, 0.1 W, 0603; Manufacturer: Vishay-Dale; CompType: Resistor; Value: 57.6k; Res_ohm: 57600; Value_Code: 57k6; Tolerance_%: 1; Power_W: 0.1; Value2: 0.1W; VDC_V: 75; TempCo: 100 ppm/C; EIA_Code: E96; U/M: EA
R31 R46 = CRCW06031K00FKEA: RES, 1.00k ohm, 1%, 0.1W, 0603; Manufacturer: Vishay-Dale; CompType: Resistor; Res_ohm: 1000; Value_Code: 1k00; Tolerance_%: 1; Power_W: 0.1; VDC_V: 75; TempCo: 100 ppm/C; EIA_Code: E96; U/M: EA
R33 = C0603C222K5RACTU: CAP, CERM, 2200 pF, 50 V, +/- 10%, X7R, 0603; Manufacturer: Kemet; Polarized: N; CompType: Capacitor; Value: 2200pF; U/M: EA; Cap_F: 0.0000000022; Tolerance_%: 10; Value1: Unknown; VDC_V: 50; Value2: 50V; TaMin_C: -55; TaMax_C: 125
R34 = CRCW060382K5FKEA: RES, 82.5 k, 1%, 0.1 W, 0603; Manufacturer: Vishay-Dale; CompType: Resistor; Value: 82.5k; Res_ohm: 82500; Value_Code: 82k5; Tolerance_%: 1; Power_W: 0.1; Value2: 0.1W; VDC_V: 75; TempCo: 100 ppm/C; EIA_Code: E96; U/M: EA
R35 R59 = CRCW060324K9FKEA: RES, 24.9 k, 1%, 0.1 W, 0603; Manufacturer: Vishay-Dale; CompType: Resistor; Value: 24.9k; Res_ohm: 24900; Value_Code: 24k9; Tolerance_%: 1; Power_W: 0.1; Value2: 0.1W; VDC_V: 75; TempCo: 100 ppm/C; EIA_Code: E96; U/M: EA
R36 = CRCW0603150KFKEA: RES, 150 k, 1%, 0.1 W, 0603; Manufacturer: Vishay-Dale; CompType: Resistor; Value: 150k; Res_ohm: 150000; Tolerance_%: 1; Power_W: 0.1; Value2: 0.1W; VDC_V: 75; TempCo: 100 ppm/C; EIA_Code: E96; U/M: EA
R38 R53 = RC0603FR-0749K9L: RES, 49.9 k, 1%, 0.1 W, 0603; Manufacturer: Yageo America; CompType: Resistor; Value: 49.9k; Res_ohm: 49900; Value_Code: 49k9; Tolerance_%: 1; Power_W: 0.1; Value2: 0.1W; VDC_V: 150; TempCo: 200 ppm/C; EIA_Code: E96; U/M: EA
R39 R54 = CRCW06033K01FKEA: RES, 3.01 k, 1%, 0.1 W, 0603; Manufacturer: Vishay-Dale; CompType: Resistor; Value: 3.01k; Res_ohm: 3010; Value_Code: 3k01; Tolerance_%: 1; Power_W: 0.1; Value2: 0.1W; VDC_V: 75; TempCo: 100 ppm/C; EIA_Code: E96; U/M: EA
R40 = CRCW060318K2FKEA: RES, 18.2 k, 1%, 0.1 W, 0603; Manufacturer: Vishay-Dale; CompType: Resistor; Value: 18.2k; Res_ohm: 18200; Value_Code: 18k2; Tolerance_%: 1; Power_W: 0.1; Value2: 0.1W; VDC_V: 75; TempCo: 100 ppm/C; EIA_Code: E96; U/M: EA
R41 R43 = CRCW0603100RFKEA: RES, 100, 1%, 0.1 W, 0603; Manufacturer: Vishay-Dale; CompType: Resistor; Value: 100; Value_Code: 100R; Tolerance_%: 1; Power_W: 0.1; Value2: 0.1W; VDC_V: 75; TempCo: 100 ppm/C; EIA_Code: E96; U/M: EA
R42 = CRCW0603243KFKEA: RES, 243 k, 1%, 0.1 W, 0603; Manufacturer: Vishay-Dale; CompType: Resistor; Value: 243k; Res_ohm: 243000; Tolerance_%: 1; Power_W: 0.1; Value2: 0.1W; VDC_V: 75; TempCo: 100 ppm/C; EIA_Code: E96; U/M: EA
R44 = CRCW06032K00FKEA: RES, 2.00 k, 1%, 0.1 W, 0603; Manufacturer: Vishay-Dale; CompType: Resistor; Value: 2.00k; Res_ohm: 2000; Value_Code: 2k00; Tolerance_%: 1; Power_W: 0.1; Value2: 0.1W; VDC_V: 75; TempCo: 100 ppm/C; EIA_Code: E96; U/M: EA
R45 = CRCW060319K1FKEA: RES, 19.1 k, 1%, 0.1 W, 0603; Manufacturer: Vishay-Dale; CompType: Resistor; Value: 19.1k; Res_ohm: 19100; Value_Code: 19k1; Tolerance_%: 1; Power_W: 0.1; Value2: 0.1W; VDC_V: 75; TempCo: 100 ppm/C; EIA_Code: E96; U/M: EA
R47 R48 R51 = CRCW060310K0FKEA: RES, 10.0 k, 1%, 0.1 W, 0603; Manufacturer: Vishay-Dale; CompType: Resistor; Value: 10.0k; Res_ohm: 10000; Value_Code: 10k0; Tolerance_%: 1; Power_W: 0.1; Value2: 0.1W; VDC_V: 75; TempCo: 100 ppm/C; EIA_Code: E96; U/M: EA
R49 = CRCW0603200RFKEA: RES, 200, 1%, 0.1 W, 0603; Manufacturer: Vishay-Dale; CompType: Resistor; Value: 200; Value_Code: 200R; Tolerance_%: 1; Power_W: 0.1; Value2: 0.1W; VDC_V: 75; TempCo: 100 ppm/C; EIA_Code: E96; U/M: EA
R50 = RC0603FR-072KL: RES, 2.00 k, 1%, 0.1 W, 0603; Manufacturer: Yageo America; CompType: Resistor; Res_ohm: 2000; Value_Code: 2k00; Tolerance_%: 1; Power_W: 0.1; Value2: 0.1W; VDC_V: 150; TempCo: 200 ppm/C; EIA_Code: E96; U/M: EA; ValueDisplayed: DNP
R52 = Resistor: RES, xxx ohm, x%, xW, [PackageReference]; Manufacturer: Used in BOM report; U/M: EA
R56 = CRCW06031K00FKEA: RES, 1.00 k, 1%, 0.1 W, 0603; Manufacturer: Vishay-Dale; CompType: Resistor; Value: 1.00k; Res_ohm: 1000; Value_Code: 1k00; Tolerance_%: 1; Power_W: 0.1; Value2: 0.1W; VDC_V: 75; TempCo: 100 ppm/C; EIA_Code: E96; U/M: EA
R57 = CRCW06030000Z0EA: RES, 0 ohm, 5%, 0.1W, 0603; Manufacturer: Vishay-Dale; CompType: Resistor; Res_ohm: 0; Value_Code: 0000; Tolerance_%: 5; Power_W: 0.1; VDC_V: 75; TempCo: 200 ppm/C; EIA_Code: E24; U/M: EA
R58 = CRCW060349R9FKEA: RES, 49.9 ohm, 1%, 0.1W, 0603; Manufacturer: Vishay-Dale; CompType: Resistor; Res_ohm: 49.9; Value_Code: 49R9; Tolerance_%: 1; Power_W: 0.1; VDC_V: 75; TempCo: 100 ppm/C; EIA_Code: E96; U/M: EA
R61 = CRCW06031M00FKEA: RES, 1.00 M, 1%, 0.1 W, 0603; Manufacturer: Vishay-Dale; CompType: Resistor; Value: 1.00Meg; Res_ohm: 1000000; Value_Code: 1M00; Tolerance_%: 1; Power_W: 0.1; Value2: 0.1W; VDC_V: 75; TempCo: 100 ppm/C; EIA_Code: E96; U/M: EA
R62 = CRCW0603200KFKEA: RES, 200 k, 1%, 0.1 W, 0603; Manufacturer: Vishay-Dale; CompType: Resistor; Value: 200k; Res_ohm: 200000; Tolerance_%: 1; Power_W: 0.1; Value2: 0.1W; VDC_V: 75; TempCo: 100 ppm/C; EIA_Code: E96; U/M: EA
R63 = CRCW060315K0FKEA: RES, 15.0 k, 1%, 0.1 W, 0603; Manufacturer: Vishay-Dale; CompType: Resistor; Value: 15.0k; Res_ohm: 15000; Value_Code: 15k0; Tolerance_%: 1; Power_W: 0.1; Value2: 0.1W; VDC_V: 75; TempCo: 100 ppm/C; EIA_Code: E96; U/M: EA
R64 = CRCW0603365KFKEA: RES, 365 k, 1%, 0.1 W, 0603; Manufacturer: Vishay-Dale; CompType: Resistor; Value: 365k; Res_ohm: 365000; Tolerance_%: 1; Power_W: 0.1; Value2: 0.1W; VDC_V: 75; TempCo: 100 ppm/C; EIA_Code: E96; U/M: EA
R65 = CRCW060311K5FKEA: RES, 11.5 k, 1%, 0.1 W, 0603; Manufacturer: Vishay-Dale; CompType: Resistor; Value: 11.5k; Res_ohm: 11500; Value_Code: 11k5; Tolerance_%: 1; Power_W: 0.1; Value2: 0.1W; VDC_V: 75; TempCo: 100 ppm/C; EIA_Code: E96; U/M: EA
R66 = CRCW06032K43FKEA: RES, 2.43 k, 1%, 0.1 W, 0603; Manufacturer: Vishay-Dale; CompType: Resistor; Value: 2.43k; Res_ohm: 2430; Value_Code: 2k43; Tolerance_%: 1; Power_W: 0.1; Value2: 0.1W; VDC_V: 75; TempCo: 100 ppm/C; EIA_Code: E96; U/M: EA
R101-R104 = CMF50432K00FHEB: RES, 432 k, 1%, 0.25 W, TH; Manufacturer: Vishay-Dale; CompType: Resistor; Value: 432k; Res_ohm: 432000; Tolerance_%: 1; Power_W: 0.25; Value2: 0.25W; VDC_V: 200; TempCo: 50 ppm/C; EIA_Code: E96; U/M: EA
RV1 = S10K275E2: Varistor 275V RMS 10MM Radial, TH; Manufacturer: EPCOS Inc; SymbolCreator: a0412235; Varistor Voltage (Min): 387V; Varistor Voltage (Typ): 430V; Varistor Voltage (Max): 473V; Current - Surge: 8kA; Number of Circuits: 1; Maximum AC Volts: 275VAC; Maximum DC Volts: 350VDC; Energy: 151J
T1 = 750315289: Transformer, 400 uH, TH; Manufacturer: Wurth Elektronik eiSos; SymbolCreator: Altium; DCR_Ohm: 0.325; Value: 400 uH; U/M: EA
T2 = 750315290: Transformer, 400 uH, TH; Manufacturer: Wurth Elektronik eiSos; SymbolCreator: Altium; DCR_Ohm: 0.322; Value: 400 uH; U/M: EA
TP1-TP3 TP5 = 1503-2: Terminal, Turret, TH, Double; Manufacturer: Keystone; CompType: Turret Terminal; U/M: EA
TP4 = 5011: Test Point, Multipurpose, Black, TH; Manufacturer: Keystone; CompType: Test Point Loop; U/M: EA
TP6-TP8 TP10 = 5000: Test Point, Miniature, Red, TH; Manufacturer: Keystone; CompType: Test Point Loop; U/M: EA
TP9 TP11 = 5001: Test Point, Miniature, Black, TH; Manufacturer: Keystone; CompType: Test Point Loop; U/M: EA
U1 = LM4040AIM3-5.0/NOPB: Precision Micropower Shunt Voltage Reference, 3-pin SOT-23, Pb-Free; Manufacturer: Texas Instruments; PackageTopMarking: R5A*XTT; PowerWise: N; CompType: Voltage Reference IC
U2 = UCC28060D: IC, Interleave PFC Controller; Manufacturer: TI; Alternate Manufacturer: None; Area: 145200
U3 = LMV358M: General Purpose, Low Voltage, R-R Out, 1MHz Dual Op Amp; Manufacturer: Texas Instruments; Characteristics: LMV358M General Purpose, Low Voltage, R-R Out, 1MHz Dual Op Amp; CompType: OpAmp IC; TaMin_C: -40.0; TaMax_C: 85.0; PowerWise: N
U4 = FOD817A: High Operating Temperature Phototransistor Optocoupler, DIP-4; Manufacturer: Fairchild Semiconductor; U/M: EA
U5 = TL431AIDBZT: Adjustable Precision Shunt Regulator, 34 ppm / degC, 100 mA, -40 to 85 degC, 3-pin SOT-23 (DBZ), Green (RoHS & no Sb/Br); Manufacturer: Texas Instruments; Alternate Manufacturer: None; Alternate PartNumber: Equivalent; Initial Accuracy @ 25/deg C(%): 1; Iout/Iz(Max)(mA): 100; Min Iz for Regulation(uA): 600; Rating: Catalog; SubFamily: Shunt Voltage Reference; Temp Coeff(Max)(ppm/ degree C): 92; Temp Coeff(Typ)(ppm/ degree C): 34; VO Adj(Max)(V): 36; VO Adj(Min)(V): 2.495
